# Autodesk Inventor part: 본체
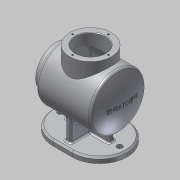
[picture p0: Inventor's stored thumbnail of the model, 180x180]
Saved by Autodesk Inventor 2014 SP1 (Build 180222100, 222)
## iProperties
Created: 2016-04
Part Number: 본체
Material: 알루미늄 6061
Document SubType Name: Modeling
Designer: SCD-A17
Density: 2.71 g/cm^3
Appearance: 알루미늄 - 평지
Mass: 913.842 g
Surface Area: 1223.62 cm^2
Volume: 337.211 cm^3
Author: SCD-A17
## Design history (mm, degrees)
sketch "스케치2"
  geometry: L1 (0, 0)-(122, 0); L2 (0, 0)-(0, 38); L3 (0, 38)-(12, 38); L4 (12, 38)-(12, 50); L5 (12, 50)-(111.087, 50); A1 r 120 centre (2, 0) between (122, 0) and (111.087, 50)
  constraints: 10 end point, 2 parallel, 2 perpendicular, 2 point on circle, 1 centre point, 1 horizontal, 1 point on line
  dimensions: "d0" = 122 distance of L1.start L1.end; "d1" = 12 distance of L2.end L3.end; "d2" = 76 diameter of L2.end L1; "d3" = 100 diameter of L4.end L1; "d4" = 240 diameter of A1
revolve "회전1" sketch "스케치2" stored, may be unused: angle "d5" = 90 deg
fillet "모깎기2" dims "d30" = 5
feature "쉘1" dims "d6" = 3
sketch "스케치3"
  geometry: C1 r 35 at (0, 0) reference; C2 r 38 at (0, 0) reference; C3 r 27 at (0, 0)
  constraints: 1 centre point, 1 coincident
  dimensions: "d7" = 54 diameter of C3
extrude "돌출1" join sketch "스케치3" distance "d8" = 15; taper "d9" = 0 deg
sketch "스케치4"
  geometry: L1 (0, -38)-(0, 38) reference; L2 (-6.5, -69)-(128.5, -69); L3 (128.5, -69)-(128.5, -79); L4 (128.5, -79)-(-6.5, -79); L5 (-6.5, -79)-(-6.5, -69); L6 (0, 0)-(122, 0); A1 r 120 centre (2, 0) between (111.087, -50) and (111.087, 50) reference; 2 further points
  constraints: 10 end point, 2 midpoint, 2 parallel, 1 horizontal, 1 perpendicular, 1 point on circle, 1 vertical alignment
  dimensions: "d10" = 79 distance from line of L4 L6.start; "d11" = 10 distance of L4.end L2.start; "d12" = 135 distance of L3.end L4.end
extrude "돌출2" join sketch "스케치4" stored distance "d13" = 100; taper "d14" = 0 deg
fillet "모깎기1" dims "d15" = 50
node "작업 평면1"
sketch "스케치5"
  geometry: L1 (35, 100)-(0, 100) reference; L2 (0, 0)-(35, 0) reference; L3 (-43.5, 12)-(-43.5, 88) reference; L4 (-31.5, 5)-(-31.5, 95) reference; C1 r 38 at (18.5, 50); A1 r 50 centre (0, 50) between (0, 100) and (0, 0) reference; A2 r 50 centre (35, 50) between (35, 0) and (35, 100) reference; 1 further point
  constraints: 1 centre point, 1 horizontal alignment, 1 midpoint
  dimensions: "d82" = 76 diameter of C1; "d84" = 50 distance from line of C1.centre L4
  node "투영된 루프1"
sketch "스케치7"
  geometry: L1 (0, 100)-(35, 100) reference; L2 (-22.5, 55)-(57.5, 55); L3 (57.5, 55)-(57.5, 45); L4 (57.5, 45)-(-22.5, 45); L5 (-22.5, 45)-(-22.5, 55); L6 (12.5, 90)-(22.5, 90); L7 (22.5, 90)-(22.5, 10); L8 (22.5, 10)-(12.5, 10); L9 (12.5, 10)-(12.5, 90); A1 r 50 centre (0, 50) between (0, 100) and (0, 0) reference; 7 further points
  constraints: 16 end point, 5 midpoint, 4 parallel, 2 horizontal, 2 horizontal alignment, 2 perpendicular, 2 vertical alignment, 1 point on circle
  dimensions: "d31" = 10 distance of L6.start L6.end; "d32" = 80 distance of L6.end L7.end; "d33" = 10 distance of L4.end L2.start; "d34" = 80 distance of L3.end L4.end
extrude "돌출5" join sketch "스케치7" stored distance "d37" = 100; taper "d38" = 0 deg
fillet "모깎기3" dims "d39" = 3
extrude "돌출6" join sketch "스케치7" stored distance "d40" = 100; taper "d41" = 0 deg
feature "면 기울기1" dims angle "d42" = 10 deg
feature "면 기울기2" dims angle "d43" = 10 deg
fillet "모깎기4" dims "d44" = 3
fillet "모깎기5" dims "d45" = 3
fillet "모깎기6" dims "d46" = 3
chamfer "모따기1" distance "d47" = 1; stored, may be unused: second distance "d48" = 2, angle "d49" = 45 deg
chamfer "모따기2" distance "d50" = 3; stored, may be unused: second distance "d51" = 2, angle "d52" = 45 deg
sketch "스케치8" dims "d53" = 65
  geometry: C1 r 38 at (0, 0) reference; C2 r 28 at (0, 0) reference; 2 further points
  constraints: 2 vertical alignment, 1 coincident, 2 other
hole "구멍2" sketch "스케치8" at (0, 32.5) diameter "d54" = 3.242; stored, may be unused: countersink angle "d58" = 90 deg, drill point angle "d60" = 118 deg; dims "d55" = 8, "d56" = 4, "d57" = 2, "d59" = 10
node "작업 평면2"
sketch "스케치10"
  geometry: 2 further points
  constraints: 1 coincident, 1 other
feature "엠보싱1" sketch "스케치10" dims "d75" = 0.5, "d76" = 0
sketch "스케치11"
  geometry: L1 (35, 0)-(0, 0) reference; L2 (0, 94)-(35, 94) reference; L3 (-47, 47)-(82, 47); L4 (17.5, 94)-(17.5, 0); C1 r 5 at (-36.5, 47); C2 r 5 at (71.5, 47); A1 r 47 centre (0, 47) between (0, 94) and (0, 0) reference; A2 r 47 centre (35, 47) between (35, 0) and (35, 94) reference; 1 further point
  constraints: 4 end point, 2 centre point, 2 horizontal alignment, 2 midpoint, 2 point on circle, 1 equal radius
  dimensions: "d77" = 10 diameter of C1; "d78" = 54 distance from line of C1.centre L4; "d79" = 54 distance from line of C2.centre L4
extrude "돌출7" cut sketch "스케치11" stored distance "d80" = 100; taper "d81" = 0 deg
extrude "돌출8" join sketch "스케치5" stored distance "d85" = 100; taper "d86" = 0 deg
hole "구멍4" diameter "d89" = 54; stored, may be unused: countersink angle "d93" = 90 deg, drill point angle "d95" = 0 deg; dims "d90" = 54, "d91" = 4, "d92" = 2, "d94" = 10, "d96" = 10, "d97" = 10
chamfer "모따기3" distance "d98" = 1; stored, may be unused: second distance "d99" = 2, angle "d100" = 45 deg
sketch "스케치12" dims "d101" = 65
  geometry: C1 r 38 at (0, 0) reference; C2 r 28 at (0, 0) reference; 3 further points
  constraints: 2 vertical alignment, 1 coincident, 2 other
hole "구멍5" sketch "스케치12" at (0, 32.5) diameter "d102" = 3.242; stored, may be unused: countersink angle "d106" = 90 deg, drill point angle "d108" = 0 deg; dims "d103" = 8, "d104" = 4, "d105" = 2, "d107" = 10
node "솔리드1"
pattern_circular "원형 패턴1" dims angle "d62" = 360 deg
pattern_circular "원형 패턴3" dims angle "d110" = 360 deg
other parameters: "d16" = -144
